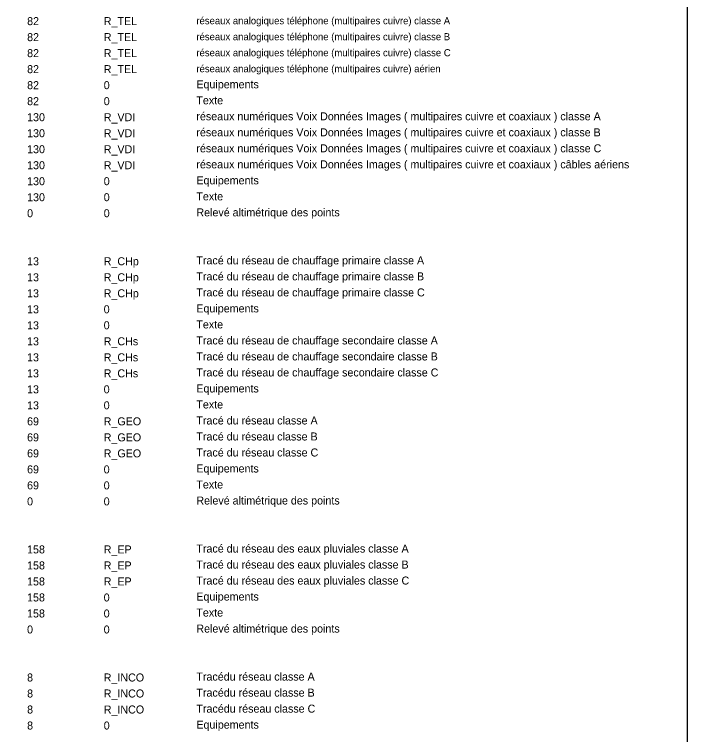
# Model space of a CAD drawing. Extents: x -60 to 214, y -380 to -21.
# Drawn here: x 72.77 to 114.84, y -290.93 to -245.94 of the extents above; entities that cross this region are included whole.
import ezdxf

# ---------------------------------------------------------------- set-up
doc = ezdxf.new("R2010")
doc.units = 0
for name, color, linetype in [('Default', 7, 'Continuous'), ('DH_TEXTE', 7, 'Continuous'), ('R_CF_ALT_POINT', 7, 'Continuous'), ('R_CF_TEL_EQUIP', 7, 'Continuous'), ('R_CF_TEL_LIAISON_CL_A', 7, 'Continuous'), ('R_CF_TEL_LIAISON_CL_B', 7, 'Continuous'), ('R_CF_TEL_LIAISON_CL_C', 7, 'Continuous'), ('R_CF_TEL_TEXTE', 7, 'Continuous'), ('R_CF_VDI_EQUIP', 7, 'Continuous'), ('R_CF_VDI_LIAISON_CL_A', 7, 'Continuous'), ('R_CF_VDI_LIAISON_CL_B', 7, 'Continuous'), ('R_CF_VDI_LIAISON_CL_C', 7, 'Continuous'), ('R_CF_VDI_TEXTE', 7, 'Continuous'), ('R_CH_ALT_POINT', 7, 'Continuous'), ('R_CH_GEOTHERMIE_CANALISATION_CL_A', 7, 'Continuous'), ('R_CH_GEOTHERMIE_CANALISATION_CL_B', 7, 'Continuous'), ('R_CH_GEOTHERMIE_CANALISATION_CL_C', 7, 'Continuous'), ('R_CH_GEOTHERMIE_EQUIP', 7, 'Continuous'), ('R_CH_GEOTHERMIE_TEXTE', 7, 'Continuous'), ('R_CH_PRIM_CANALISATION_CL_A', 7, 'Continuous'), ('R_CH_PRIM_CANALISATION_CL_B', 7, 'Continuous'), ('R_CH_PRIM_CANALISATION_CL_C', 7, 'Continuous'), ('R_CH_PRIM_EQUIP', 7, 'Continuous'), ('R_CH_PRIM_TEXTE', 7, 'Continuous'), ('R_CH_SECOND_CANALISATION_CL_A', 7, 'Continuous'), ('R_CH_SECOND_CANALISATION_CL_B', 7, 'Continuous'), ('R_CH_SECOND_CANALISATION_CL_C', 7, 'Continuous'), ('R_CH_SECOND_EQUIP', 7, 'Continuous'), ('R_CH_SECOND_TEXTE', 7, 'Continuous'), ('R_INCONNU_CANALISATION_CL_A', 7, 'Continuous'), ('R_INCONNU_CANALISATION_CL_B', 7, 'Continuous'), ('R_INCONNU_CANALISATION_CL_C', 7, 'Continuous'), ('R_INCONNU_EQUIP', 7, 'Continuous'), ('R_PLU_ALT_POINT', 7, 'Continuous'), ('R_PLU_CANALISATION_CL_A', 7, 'Continuous'), ('R_PLU_CANALISATION_CL_B', 7, 'Continuous'), ('R_PLU_CANALISATION_CL_C', 7, 'Continuous'), ('R_PLU_EQUIP', 7, 'Continuous'), ('R_PLU_TEXTE', 7, 'Continuous')]:
    doc.layers.add(name, color=color, linetype=linetype)

msp = doc.modelspace()

# ---------------------------------------------------------------- linework, layer by layer
at = {"layer": 'Default'}
msp.add_lwpolyline([(114.838, -25.727), (33.073, -25.727), (33.073, -380.216), (114.838, -380.216)], close=True, dxfattribs=at)

# ---------------------------------------------------------------- texts
at = {"layer": 'DH_TEXTE'}
for s, height, p in [('82 ', 0.5, (73.561, -249.61)), ('R_TEL ', 0.5, (78.351, -249.61)), ('réseaux analogiques téléphone (multipaires cuivre) aérien', 0.44444, (84.14, -249.555)), ('réseaux numériques Voix Données Images ( multipaires cuivre et coaxiaux ) câbles aériens ', 0.5, (84.14, -255.555)), ('130 ', 0.5, (73.561, -255.61)), ('R_VDI ', 0.5, (78.351, -255.61))]:
    msp.add_text(s, height=height, dxfattribs=at).set_placement(p)
at = {"layer": 'R_CF_ALT_POINT'}
for s, p in [('0 ', (73.561, -258.61)), ('0 ', (78.351, -258.61)), ('Relevé altimétrique des points ', (84.14, -258.555))]:
    msp.add_text(s, height=0.5, dxfattribs=at).set_placement(p)
at = {"layer": 'R_CF_TEL_EQUIP'}
for s, p in [('82 ', (73.561, -250.61)), ('0 ', (78.351, -250.61)), ('Equipements ', (84.14, -250.555))]:
    msp.add_text(s, height=0.5, dxfattribs=at).set_placement(p)
at = {"layer": 'R_CF_TEL_LIAISON_CL_A'}
for s, height, p in [('réseaux analogiques téléphone (multipaires cuivre) classe A ', 0.44444, (84.14, -246.555)), ('82 ', 0.5, (73.561, -246.61)), ('R_TEL ', 0.5, (78.351, -246.61))]:
    msp.add_text(s, height=height, dxfattribs=at).set_placement(p)
at = {"layer": 'R_CF_TEL_LIAISON_CL_B'}
for s, height, p in [('82 ', 0.5, (73.561, -247.61)), ('R_TEL ', 0.5, (78.351, -247.61)), ('réseaux analogiques téléphone (multipaires cuivre) classe B', 0.44444, (84.14, -247.555))]:
    msp.add_text(s, height=height, dxfattribs=at).set_placement(p)
at = {"layer": 'R_CF_TEL_LIAISON_CL_C'}
for s, height, p in [('82 ', 0.5, (73.561, -248.61)), ('R_TEL ', 0.5, (78.351, -248.61)), ('réseaux analogiques téléphone (multipaires cuivre) classe C', 0.44444, (84.14, -248.555))]:
    msp.add_text(s, height=height, dxfattribs=at).set_placement(p)
at = {"layer": 'R_CF_TEL_TEXTE'}
for s, p in [('82 ', (73.561, -251.61)), ('0 ', (78.351, -251.61)), ('Texte ', (84.14, -251.555))]:
    msp.add_text(s, height=0.5, dxfattribs=at).set_placement(p)
at = {"layer": 'R_CF_VDI_EQUIP'}
for s, p in [('130 ', (73.561, -256.61)), ('0 ', (78.351, -256.61)), ('Equipements ', (84.14, -256.555))]:
    msp.add_text(s, height=0.5, dxfattribs=at).set_placement(p)
at = {"layer": 'R_CF_VDI_LIAISON_CL_A'}
for s, p in [('130 ', (73.561, -252.61)), ('R_VDI ', (78.351, -252.61)), ('réseaux numériques Voix Données Images ( multipaires cuivre et coaxiaux ) classe A ', (84.14, -252.555))]:
    msp.add_text(s, height=0.5, dxfattribs=at).set_placement(p)
at = {"layer": 'R_CF_VDI_LIAISON_CL_B'}
for s, p in [('130 ', (73.561, -253.61)), ('R_VDI ', (78.351, -253.61)), ('réseaux numériques Voix Données Images ( multipaires cuivre et coaxiaux ) classe B ', (84.14, -253.555))]:
    msp.add_text(s, height=0.5, dxfattribs=at).set_placement(p)
at = {"layer": 'R_CF_VDI_LIAISON_CL_C'}
for s, p in [('130 ', (73.561, -254.61)), ('R_VDI ', (78.351, -254.61)), ('réseaux numériques Voix Données Images ( multipaires cuivre et coaxiaux ) classe C ', (84.14, -254.555))]:
    msp.add_text(s, height=0.5, dxfattribs=at).set_placement(p)
at = {"layer": 'R_CF_VDI_TEXTE'}
for s, p in [('130 ', (73.561, -257.61)), ('0 ', (78.351, -257.61)), ('Texte ', (84.14, -257.555))]:
    msp.add_text(s, height=0.5, dxfattribs=at).set_placement(p)
at = {"layer": 'R_CH_ALT_POINT'}
for s, p in [('0', (73.559, -276.61)), ('0 ', (78.348, -276.61)), ('Relevé altimétrique des points ', (84.138, -276.555))]:
    msp.add_text(s, height=0.5, dxfattribs=at).set_placement(p)
at = {"layer": 'R_CH_GEOTHERMIE_CANALISATION_CL_A'}
for s, p in [('69 ', (73.559, -271.61)), ('R_GEO ', (78.348, -271.61)), ('Tracé du réseau classe A ', (84.138, -271.555))]:
    msp.add_text(s, height=0.5, dxfattribs=at).set_placement(p)
at = {"layer": 'R_CH_GEOTHERMIE_CANALISATION_CL_B'}
for s, p in [('69 ', (73.559, -272.61)), ('R_GEO ', (78.348, -272.61)), ('Tracé du réseau classe B ', (84.138, -272.555))]:
    msp.add_text(s, height=0.5, dxfattribs=at).set_placement(p)
at = {"layer": 'R_CH_GEOTHERMIE_CANALISATION_CL_C'}
for s, p in [('Tracé du réseau classe C ', (84.138, -273.555)), ('69 ', (73.559, -273.61)), ('R_GEO ', (78.348, -273.61))]:
    msp.add_text(s, height=0.5, dxfattribs=at).set_placement(p)
at = {"layer": 'R_CH_GEOTHERMIE_EQUIP'}
for s, p in [('69 ', (73.559, -274.61)), ('0 ', (78.348, -274.61)), ('Equipements  ', (84.138, -274.555))]:
    msp.add_text(s, height=0.5, dxfattribs=at).set_placement(p)
at = {"layer": 'R_CH_GEOTHERMIE_TEXTE'}
for s, p in [('69 ', (73.559, -275.61)), ('0 ', (78.348, -275.61)), ('Texte ', (84.138, -275.555))]:
    msp.add_text(s, height=0.5, dxfattribs=at).set_placement(p)
at = {"layer": 'R_CH_PRIM_CANALISATION_CL_A'}
for s, p in [('13 ', (73.559, -261.61)), ('R_CHp ', (78.348, -261.61)), ('Tracé du réseau de chauffage primaire classe A ', (84.138, -261.555))]:
    msp.add_text(s, height=0.5, dxfattribs=at).set_placement(p)
at = {"layer": 'R_CH_PRIM_CANALISATION_CL_B'}
for s, p in [('13 ', (73.559, -262.61)), ('R_CHp ', (78.348, -262.61)), ('Tracé du réseau de chauffage primaire classe B ', (84.138, -262.555))]:
    msp.add_text(s, height=0.5, dxfattribs=at).set_placement(p)
at = {"layer": 'R_CH_PRIM_CANALISATION_CL_C'}
for s, p in [('13 ', (73.559, -263.61)), ('R_CHp ', (78.348, -263.61)), ('Tracé du réseau de chauffage primaire classe C ', (84.138, -263.555))]:
    msp.add_text(s, height=0.5, dxfattribs=at).set_placement(p)
at = {"layer": 'R_CH_PRIM_EQUIP'}
for s, p in [('Equipements ', (84.138, -264.555)), ('13 ', (73.559, -264.61)), ('0 ', (78.348, -264.61))]:
    msp.add_text(s, height=0.5, dxfattribs=at).set_placement(p)
at = {"layer": 'R_CH_PRIM_TEXTE'}
for s, p in [('13 ', (73.559, -265.61)), ('0 ', (78.348, -265.61)), ('Texte ', (84.138, -265.555))]:
    msp.add_text(s, height=0.5, dxfattribs=at).set_placement(p)
at = {"layer": 'R_CH_SECOND_CANALISATION_CL_A'}
for s, p in [('13 ', (73.559, -266.61)), ('R_CHs ', (78.348, -266.61)), ('Tracé du réseau de chauffage secondaire classe A ', (84.138, -266.555))]:
    msp.add_text(s, height=0.5, dxfattribs=at).set_placement(p)
at = {"layer": 'R_CH_SECOND_CANALISATION_CL_B'}
for s, p in [('13 ', (73.559, -267.61)), ('R_CHs ', (78.348, -267.61)), ('Tracé du réseau de chauffage secondaire classe B ', (84.138, -267.555))]:
    msp.add_text(s, height=0.5, dxfattribs=at).set_placement(p)
at = {"layer": 'R_CH_SECOND_CANALISATION_CL_C'}
for s, p in [('13 ', (73.559, -268.61)), ('R_CHs ', (78.348, -268.61)), ('Tracé du réseau de chauffage secondaire classe C ', (84.138, -268.555))]:
    msp.add_text(s, height=0.5, dxfattribs=at).set_placement(p)
at = {"layer": 'R_CH_SECOND_EQUIP'}
for s, p in [('13 ', (73.559, -269.61)), ('0 ', (78.348, -269.61)), ('Equipements ', (84.138, -269.555))]:
    msp.add_text(s, height=0.5, dxfattribs=at).set_placement(p)
at = {"layer": 'R_CH_SECOND_TEXTE'}
for s, p in [('13 ', (73.559, -270.61)), ('0 ', (78.348, -270.61)), ('Texte ', (84.138, -270.555))]:
    msp.add_text(s, height=0.5, dxfattribs=at).set_placement(p)
at = {"layer": 'R_INCONNU_CANALISATION_CL_A'}
for s, p in [('Tracédu réseau classe A ', (84.138, -287.555)), ('8 ', (73.559, -287.61)), ('R_INCO ', (78.348, -287.61))]:
    msp.add_text(s, height=0.5, dxfattribs=at).set_placement(p)
at = {"layer": 'R_INCONNU_CANALISATION_CL_B'}
for s, p in [('8 ', (73.561, -288.61)), ('R_INCO ', (78.351, -288.61)), ('Tracédu réseau classe B ', (84.14, -288.555))]:
    msp.add_text(s, height=0.5, dxfattribs=at).set_placement(p)
at = {"layer": 'R_INCONNU_CANALISATION_CL_C'}
for s, p in [('8 ', (73.561, -289.61)), ('R_INCO ', (78.351, -289.61)), ('Tracédu réseau classe C ', (84.14, -289.555))]:
    msp.add_text(s, height=0.5, dxfattribs=at).set_placement(p)
at = {"layer": 'R_INCONNU_EQUIP'}
for s, p in [('8 ', (73.561, -290.61)), ('0 ', (78.351, -290.61)), ('Equipements ', (84.14, -290.555))]:
    msp.add_text(s, height=0.5, dxfattribs=at).set_placement(p)
at = {"layer": 'R_PLU_ALT_POINT'}
for s, p in [('0 ', (73.559, -284.61)), ('0 ', (78.348, -284.61)), ('Relevé altimétrique des points ', (84.138, -284.555))]:
    msp.add_text(s, height=0.5, dxfattribs=at).set_placement(p)
at = {"layer": 'R_PLU_CANALISATION_CL_A'}
for s, p in [('158 ', (73.559, -279.61)), ('R_EP ', (78.348, -279.61)), ('Tracé du réseau des eaux pluviales classe A ', (84.138, -279.555))]:
    msp.add_text(s, height=0.5, dxfattribs=at).set_placement(p)
at = {"layer": 'R_PLU_CANALISATION_CL_B'}
for s, p in [('158 ', (73.559, -280.61)), ('R_EP ', (78.348, -280.61)), ('Tracé du réseau des eaux pluviales classe B ', (84.138, -280.555))]:
    msp.add_text(s, height=0.5, dxfattribs=at).set_placement(p)
at = {"layer": 'R_PLU_CANALISATION_CL_C'}
for s, p in [('158 ', (73.559, -281.61)), ('R_EP ', (78.348, -281.61)), ('Tracé du réseau des eaux pluviales classe C ', (84.138, -281.555))]:
    msp.add_text(s, height=0.5, dxfattribs=at).set_placement(p)
at = {"layer": 'R_PLU_EQUIP'}
for s, p in [('Equipements ', (84.138, -282.555)), ('158 ', (73.559, -282.61)), ('0 ', (78.348, -282.61))]:
    msp.add_text(s, height=0.5, dxfattribs=at).set_placement(p)
at = {"layer": 'R_PLU_TEXTE'}
for s, p in [('158 ', (73.559, -283.61)), ('0 ', (78.348, -283.61)), ('Texte ', (84.138, -283.555))]:
    msp.add_text(s, height=0.5, dxfattribs=at).set_placement(p)

doc.saveas('drawing.dxf')
